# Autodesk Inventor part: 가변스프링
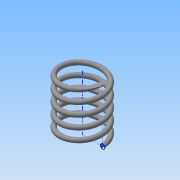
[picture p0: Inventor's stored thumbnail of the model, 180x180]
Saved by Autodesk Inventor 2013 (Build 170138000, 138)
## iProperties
Created: 2018-12
Part Number: 가변스프링
Material: Generic
Document SubType Name: Modeling
Designer: Administrator
Density: 1 g/cm^3
Author: Administrator
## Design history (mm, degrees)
sketch "스케치3"
  geometry: L1 (0, 0)-(9, 0); L2 (9, 0)-(9, 24.5); L3 (9, 24.5)-(0, 24.5); L4 (0, 24.5)-(0, 0); C1 r 1 at (9, 0)
  constraints: 8 end point, 2 parallel, 1 centre point, 1 coincident, 1 horizontal, 1 perpendicular
  dimensions: "d2" = 24.5 distance of L1.end L2.end (derived); "d4" = 18 diameter of L2 L4; "d5" = 2 diameter of C1
feature "코일1" pitch "d6" = 10; turns "d8" = 5; dims "d7" = 24.5 (= d2), "d9" = 0, angle "d10" = 90 deg, angle "d11" = 90 deg, "d12" = 0, "d13" = 0
sketch "스케치4"
  geometry: C1 r 14.844 at (0, 0); 1 further point
  constraints: 1 centre point, 1 coincident
extrude "돌출1" sketch "스케치4" distance "d14" = 24.5 (= d2); taper "d15" = 0 deg
node "솔리드1"
